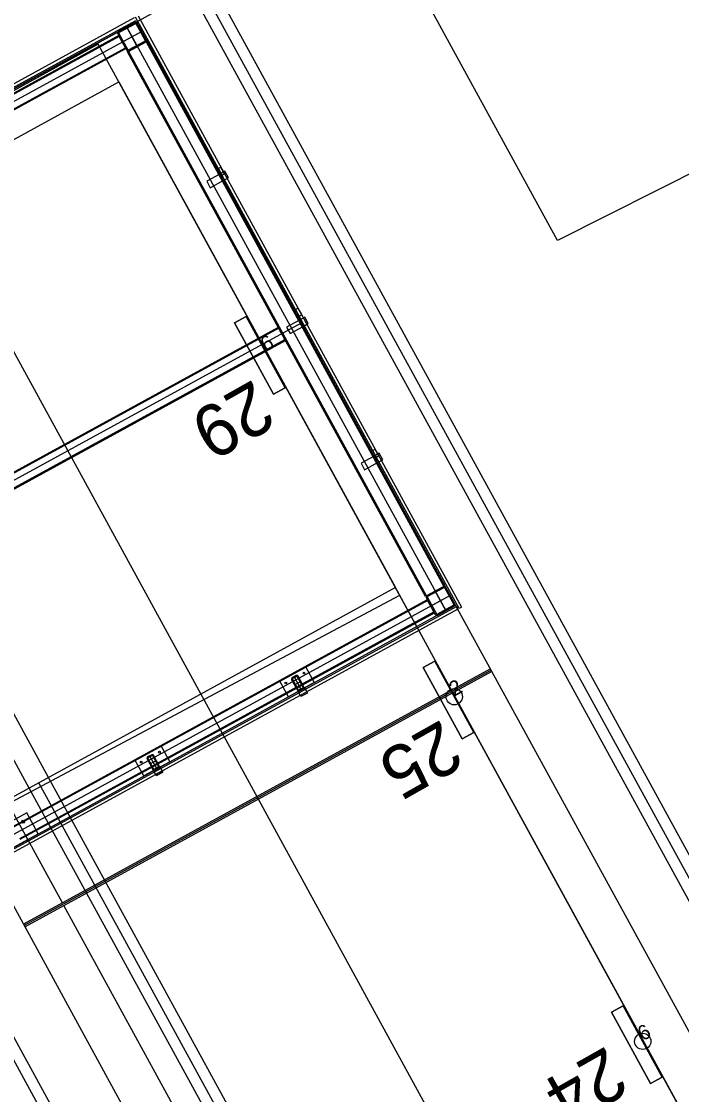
# Model space of a CAD drawing. Extents: x -783978 to -783565, y -1064821 to -1064596.
# Drawn here: x -783735.98 to -783731.52, y -1064671.69 to -1064664.43 of the extents above; entities that cross this region are included whole.
import ezdxf

# ---------------------------------------------------------------- set-up
doc = ezdxf.new("R2010")
doc.units = 0
for name, color, linetype in [('Default', 7, 'Continuous'), ('PS 01_01_10', 7, 'Continuous'), ('SO 01_20_01', 7, 'Continuous'), ('SO 01_50_01', 7, 'Continuous'), ('SO 01_74_01', 7, 'Continuous'), ('SO 01_86_04', 7, 'Continuous')]:
    doc.layers.add(name, color=color, linetype=linetype)

# ---------------------------------------------------------------- blocks, each defined once
blk = doc.blocks.new('POINT_DISPLAY')
at = {"layer": 'Default'}
blk.add_line((0, 0), (0, 0), dxfattribs=at)

msp = doc.modelspace()

# ---------------------------------------------------------------- linework, layer by layer
at = {"layer": 'PS 01_01_10'}
msp.add_lwpolyline([(-783718.9415, -1064658.9356), (-783725.9639, -1064662.6889), (-783732.3538, -1064665.9121), (-783735.2095, -1064660.6967), (-783789.362, -1064690.3481), (-783783.8255, -1064700.4409), (-783871.4362, -1064748.4249), (-783875.857, -1064749.8347)], dxfattribs=at)
at = {"layer": 'SO 01_20_01'}
for p, q in [((-783726.9264, -1064683.3119), (-783738.1468, -1064662.8034)), ((-783728.4298, -1064675.772), (-783734.7655, -1064664.1918)), ((-783728.357, -1064675.7488), (-783734.6997, -1064664.1558)), ((-783728.4886, -1064675.8208), (-783734.8312, -1064664.2278)), ((-783735.2041, -1064664.4318), (-783786.7885, -1064692.6541)), ((-783733.0442, -1064668.3796), (-783735.2041, -1064664.4318)), ((-783786.6445, -1064692.9173), (-783735.3233, -1064664.839)), ((-783735.3233, -1064664.839), (-783733.4514, -1064668.2604)), ((-783735.7981, -1064669.5443), (-783737.67, -1064666.1229)), ((-783735.9297, -1064669.6163), (-783737.8016, -1064666.1949)), ((-783733.4514, -1064668.2604), (-783745.2333, -1064674.7064)), ((-783733.0722, -1064668.9535), (-783733.4514, -1064668.2604)), ((-783745.0893, -1064674.9696), (-783733.0442, -1064668.3796)), ((-783726.0127, -1064681.2318), (-783733.0442, -1064668.3796)), ((-783732.809, -1064668.8095), (-783735.9673, -1064670.5374)), ((-783732.8042, -1064668.8182), (-783735.9625, -1064670.5461)), ((-783732.7994, -1064668.827), (-783735.9577, -1064670.5549)), ((-783726.2758, -1064681.3758), (-783733.0626, -1064668.971)), ((-783728.2804, -1064683.4414), (-783735.8639, -1064669.5803)), ((-783728.2146, -1064683.4054), (-783735.7981, -1064669.5443)), ((-783728.3462, -1064683.4774), (-783735.9297, -1064669.6163)), ((-783735.7041, -1064670.3934), (-783736.0833, -1064669.7003)), ((-783729.1709, -1064682.9597), (-783736.2025, -1064670.1075)), ((-783732.4653, -1064677.9799), (-783736.6411, -1064670.3475)), ((-783732.3925, -1064677.9567), (-783736.5753, -1064670.3115)), ((-783728.9074, -1064682.8156), (-783735.6946, -1064670.411))]:
    msp.add_line(p, q, dxfattribs=at)
at = {"layer": 'SO 01_50_01'}
for p, q in [((-783786.7885, -1064692.6541), (-783725.4827, -1064659.1131)), ((-783738.5378, -1064666.2557), (-783734.1523, -1064663.8564)), ((-783738.5378, -1064666.2558), (-783734.1522, -1064663.8565)), ((-783738.5378, -1064666.2558), (-783734.1522, -1064663.8565))]:
    msp.add_line(p, q, dxfattribs=at)
at = {"layer": 'SO 01_74_01'}
for p, q in [((-783735.2185, -1064664.4055), (-783786.6099, -1064692.5222)), ((-783786.6003, -1064692.5398), (-783735.2089, -1064664.423)), ((-783733.0211, -1064668.4011), (-783735.2097, -1064664.4007)), ((-783735.1922, -1064664.3911), (-783733.0035, -1064668.3915)), ((-783735.3237, -1064664.5257), (-783738.1265, -1064666.0592)), ((-783735.3207, -1064664.5313), (-783738.1235, -1064666.0647)), ((-783735.2757, -1064664.6135), (-783735.3237, -1064664.5257)), ((-783735.2787, -1064664.608), (-783735.3207, -1064664.5313)), ((-783735.2637, -1064664.6354), (-783735.1321, -1064664.5634)), ((-783735.2567, -1064664.6316), (-783735.1391, -1064664.5673)), ((-783735.1391, -1064664.5673), (-783733.1232, -1064668.2518)), ((-783735.1321, -1064664.5634), (-783733.1162, -1064668.248)), ((-783738.0815, -1064666.1414), (-783735.2787, -1064664.608)), ((-783738.0785, -1064666.1469), (-783735.2757, -1064664.6135)), ((-783733.2478, -1064668.32), (-783735.2637, -1064664.6354)), ((-783733.2408, -1064668.3162), (-783735.2567, -1064664.6316)), ((-783734.6318, -1064665.4153), (-783734.6494, -1064665.4249)), ((-783734.6494, -1064665.4249), (-783734.6254, -1064665.4688)), ((-783734.605, -1064665.4434), (-783734.6401, -1064665.4626)), ((-783734.6078, -1064665.4592), (-783734.6318, -1064665.4153)), ((-783734.581, -1064665.4873), (-783734.605, -1064665.4434)), ((-783734.6401, -1064665.4626), (-783734.6161, -1064665.5065)), ((-783734.6254, -1064665.4688), (-783734.6078, -1064665.4592)), ((-783734.6161, -1064665.5065), (-783734.581, -1064665.4873)), ((-783734.1098, -1064666.3694), (-783734.1274, -1064666.379)), ((-783734.1274, -1064666.379), (-783734.1034, -1064666.4228)), ((-783734.0858, -1064666.4132), (-783734.1098, -1064666.3694)), ((-783734.1034, -1064666.4228), (-783734.0858, -1064666.4132)), ((-783734.0651, -1064666.4304), (-783734.1002, -1064666.4496)), ((-783734.1002, -1064666.4496), (-783734.0762, -1064666.4934)), ((-783734.0411, -1064666.4742), (-783734.0651, -1064666.4304)), ((-783734.2438, -1064666.4996), (-783737.0465, -1064668.0331)), ((-783734.2407, -1064666.5052), (-783737.0435, -1064668.0386)), ((-783734.1958, -1064666.5874), (-783734.2438, -1064666.4996)), ((-783734.1988, -1064666.5818), (-783734.2407, -1064666.5052)), ((-783734.0762, -1064666.4934), (-783734.0411, -1064666.4742)), ((-783737.0016, -1064668.1153), (-783734.1988, -1064666.5818)), ((-783736.9985, -1064668.1208), (-783734.1958, -1064666.5874)), ((-783733.5879, -1064667.3234), (-783733.6054, -1064667.333)), ((-783733.6054, -1064667.333), (-783733.5814, -1064667.3769)), ((-783733.5639, -1064667.3673), (-783733.5879, -1064667.3234)), ((-783733.5611, -1064667.3515), (-783733.5962, -1064667.3707)), ((-783733.5962, -1064667.3707), (-783733.5722, -1064667.4146)), ((-783733.5814, -1064667.3769), (-783733.5639, -1064667.3673)), ((-783733.5722, -1064667.4146), (-783733.5371, -1064667.3954)), ((-783733.5371, -1064667.3954), (-783733.5611, -1064667.3515)), ((-783733.1162, -1064668.248), (-783733.2478, -1064668.32)), ((-783733.1232, -1064668.2518), (-783733.2408, -1064668.3162)), ((-783733.2358, -1064668.3419), (-783736.0386, -1064669.8754)), ((-783733.2328, -1064668.3475), (-783736.0356, -1064669.8809)), ((-783733.1878, -1064668.4297), (-783733.2358, -1064668.3419)), ((-783733.1908, -1064668.4241), (-783733.2328, -1064668.3475)), ((-783744.8433, -1064674.8464), (-783733.0394, -1064668.3884)), ((-783733.0298, -1064668.4059), (-783744.8337, -1064674.8639)), ((-783733.0394, -1064668.3884), (-783733.0298, -1064668.4059)), ((-783733.0035, -1064668.3915), (-783733.0211, -1064668.4011)), ((-783735.9936, -1064669.9576), (-783733.1908, -1064668.4241)), ((-783735.9906, -1064669.9631), (-783733.1878, -1064668.4297)), ((-783734.1101, -1064668.9628), (-783734.0663, -1064668.9388)), ((-783734.0909, -1064668.9979), (-783734.1101, -1064668.9628)), ((-783734.1053, -1064668.9715), (-783734.0615, -1064668.9475)), ((-783734.0957, -1064668.9891), (-783734.1053, -1064668.9715)), ((-783734.0519, -1064668.9651), (-783734.0957, -1064668.9891)), ((-783734.0471, -1064668.9739), (-783734.0909, -1064668.9979)), ((-783734.0663, -1064668.9388), (-783734.0471, -1064668.9739)), ((-783734.0615, -1064668.9475), (-783734.0519, -1064668.9651)), ((-783735.0883, -1064669.4979), (-783735.0444, -1064669.4739)), ((-783735.0691, -1064669.533), (-783735.0883, -1064669.4979)), ((-783735.0835, -1064669.5067), (-783735.0396, -1064669.4827)), ((-783735.0739, -1064669.5243), (-783735.0835, -1064669.5067)), ((-783735.03, -1064669.5003), (-783735.0739, -1064669.5243)), ((-783735.0252, -1064669.509), (-783735.0691, -1064669.533)), ((-783735.0444, -1064669.4739), (-783735.0252, -1064669.509)), ((-783735.0396, -1064669.4827), (-783735.03, -1064669.5003))]:
    msp.add_line(p, q, dxfattribs=at)
for points in [[(-783735.1681, -1064664.4976), (-783787.4762, -1064693.1159)], [(-783735.2146, -1064664.4376), (-783735.3252, -1064664.4981)], [(-783735.2108, -1064664.4446), (-783735.3213, -1064664.5051)], [(-783735.1681, -1064664.4976), (-783735.2997, -1064664.5696)], [(-783735.2699, -1064664.4678), (-783733.11, -1064668.4156)], [(-783735.1979, -1064664.5994), (-783735.2699, -1064664.4678)], [(-783735.1449, -1064664.5567), (-783735.2054, -1064664.4462)], [(-783735.1379, -1064664.5529), (-783735.1983, -1064664.4423)], [(-783735.3299, -1064664.5143), (-783735.2695, -1064664.6249)], [(-783735.3229, -1064664.5105), (-783735.2624, -1064664.621)], [(-783735.257, -1064664.6226), (-783735.1465, -1064664.5622)], [(-783735.2532, -1064664.6297), (-783735.1426, -1064664.5692)], [(-783734.0882, -1064666.4715), (-783786.3963, -1064695.0898)], [(-783733.1268, -1064668.2538), (-783733.2373, -1064668.3142)], [(-783733.1229, -1064668.2608), (-783733.2334, -1064668.3213)], [(-783733.057, -1064668.3729), (-783733.1175, -1064668.2624)], [(-783733.05, -1064668.3691), (-783733.1105, -1064668.2585)], [(-783733.0802, -1064668.3138), (-783745.8491, -1064675.2998)], [(-783733.2421, -1064668.3305), (-783733.1816, -1064668.4411)], [(-783733.235, -1064668.3267), (-783733.1746, -1064668.4372)], [(-783733.0802, -1064668.3138), (-783733.2118, -1064668.3858)], [(-783733.11, -1064668.4156), (-783733.182, -1064668.284)], [(-783733.1691, -1064668.4388), (-783733.0586, -1064668.3783)], [(-783733.1653, -1064668.4458), (-783733.0548, -1064668.3854)], [(-783734.1226, -1064668.8556), (-783734.1498, -1064668.8705)], [(-783734.1536, -1064668.8833), (-783734.1147, -1064668.9545)], [(-783734.1481, -1064668.8803), (-783734.1091, -1064668.9515)], [(-783734.1195, -1064668.8611), (-783734.1468, -1064668.876)], [(-783734.1362, -1064668.863), (-783734.0882, -1064668.9508)], [(-783734.0903, -1064668.8949), (-783734.1341, -1064668.9189)], [(-783734.0763, -1064668.9335), (-783734.1153, -1064668.8624)], [(-783734.0708, -1064668.9305), (-783734.1097, -1064668.8593)], [(-783734.1049, -1064668.9527), (-783734.0776, -1064668.9378)], [(-783734.1018, -1064668.9582), (-783734.0746, -1064668.9433)], [(-783735.1318, -1064669.4185), (-783735.0928, -1064669.4896)], [(-783735.1007, -1064669.3907), (-783735.128, -1064669.4057)], [(-783735.1262, -1064669.4155), (-783735.0873, -1064669.4866)], [(-783735.0977, -1064669.3963), (-783735.125, -1064669.4112)], [(-783735.1144, -1064669.3982), (-783735.0664, -1064669.4859)], [(-783735.0684, -1064669.4301), (-783735.1123, -1064669.4541)], [(-783735.0545, -1064669.4687), (-783735.0934, -1064669.3975)], [(-783735.049, -1064669.4656), (-783735.0879, -1064669.3945)], [(-783735.083, -1064669.4879), (-783735.0558, -1064669.4729)], [(-783735.08, -1064669.4934), (-783735.0527, -1064669.4785)]]:
    msp.add_lwpolyline(points, dxfattribs=at)
for points in [[(-783734.6161, -1064665.5065), (-783734.6401, -1064665.4626), (-783734.7279, -1064665.5106), (-783734.7039, -1064665.5545)], [(-783734.0762, -1064666.4934), (-783734.1002, -1064666.4496), (-783734.1879, -1064666.4976), (-783734.1639, -1064666.5414)], [(-783733.5722, -1064667.4146), (-783733.5962, -1064667.3707), (-783733.6839, -1064667.4187), (-783733.6599, -1064667.4626)], [(-783734.0005, -1064668.9028), (-783734.1759, -1064668.9988), (-783734.2335, -1064668.8935), (-783734.0581, -1064668.7975)], [(-783734.9786, -1064669.4379), (-783735.1541, -1064669.5339), (-783735.2117, -1064669.4287), (-783735.0362, -1064669.3327)], [(-783735.9459, -1064669.7847), (-783736.2968, -1064669.9767), (-783736.22, -1064670.1171), (-783735.8691, -1064669.9251)]]:
    msp.add_lwpolyline(points, close=True, dxfattribs=at)
for centre, radius in [((-783734.07, -1064668.8382), 0.006), ((-783734.1928, -1064668.9054), 0.006), ((-783735.171, -1064669.4406), 0.006), ((-783735.0482, -1064669.3734), 0.006), ((-783735.9705, -1064669.8438), 0.01)]:
    msp.add_circle(centre, radius, dxfattribs=at)
for centre, radius, start, end in [((-783735.3194, -1064664.5086), 0.012, 118.68349, 208.68349), ((-783735.2089, -1064664.4481), 0.012, 28.68349, 118.68349), ((-783735.2089, -1064664.4481), 0.004, 28.68349, 118.68349), ((-783735.3194, -1064664.5086), 0.004, 118.68349, 208.68349), ((-783735.1484, -1064664.5586), 0.004, 298.68349, 28.68349), ((-783735.1484, -1064664.5586), 0.012, 298.68349, 28.68349), ((-783735.2589, -1064664.6191), 0.012, 208.68349, 298.68349), ((-783735.2589, -1064664.6191), 0.004, 208.68349, 298.68349), ((-783733.121, -1064668.2643), 0.012, 28.68349, 118.68349), ((-783733.121, -1064668.2643), 0.004, 28.68349, 118.68349), ((-783733.2315, -1064668.3248), 0.012, 118.68349, 208.68349), ((-783733.2315, -1064668.3248), 0.004, 118.68349, 208.68349), ((-783733.0605, -1064668.3748), 0.004, 298.68349, 28.68349), ((-783733.0605, -1064668.3748), 0.012, 298.68349, 28.68349), ((-783733.1711, -1064668.4353), 0.012, 208.68349, 298.68349), ((-783733.1711, -1064668.4353), 0.004, 208.68349, 298.68349), ((-783734.118, -1064668.8639), 0.00945, 28.68349, 118.68349), ((-783734.1453, -1064668.8788), 0.00945, 118.68349, 208.68349), ((-783734.1453, -1064668.8788), 0.00315, 118.68349, 208.68349), ((-783734.118, -1064668.8639), 0.00315, 28.68349, 118.68349), ((-783734.1064, -1064668.9499), 0.00945, 208.68349, 298.68349), ((-783734.1064, -1064668.9499), 0.00315, 208.68349, 298.68349), ((-783734.0791, -1064668.935), 0.00315, 298.68349, 28.68349), ((-783734.0791, -1064668.935), 0.00945, 298.68349, 28.68349), ((-783735.1235, -1064669.414), 0.00945, 118.68349, 208.68349), ((-783735.1235, -1064669.414), 0.00315, 118.68349, 208.68349), ((-783735.0962, -1064669.399), 0.00945, 28.68349, 118.68349), ((-783735.0962, -1064669.399), 0.00315, 28.68349, 118.68349), ((-783735.0845, -1064669.4851), 0.00945, 208.68349, 298.68349), ((-783735.0845, -1064669.4851), 0.00315, 208.68349, 298.68349), ((-783735.0573, -1064669.4702), 0.00315, 298.68349, 28.68349), ((-783735.0573, -1064669.4702), 0.00945, 298.68349, 28.68349)]:
    msp.add_arc(centre, radius, start, end, dxfattribs=at)
at = {"layer": 'SO 01_86_04'}
for p, q in [((-783734.5403, -1064666.4684), (-783734.4614, -1064666.4252)), ((-783734.4614, -1064666.4252), (-783734.5403, -1064666.4684)), ((-783734.5403, -1064666.4684), (-783734.4614, -1064666.4252)), ((-783734.4614, -1064666.4252), (-783734.5403, -1064666.4684)), ((-783734.4614, -1064666.4252), (-783734.1974, -1064666.9077)), ((-783734.1974, -1064666.9077), (-783734.4614, -1064666.4252)), ((-783734.4614, -1064666.4252), (-783734.1974, -1064666.9077)), ((-783734.1974, -1064666.9077), (-783734.4614, -1064666.4252)), ((-783734.2763, -1064666.9509), (-783734.5403, -1064666.4684)), ((-783734.5403, -1064666.4684), (-783734.2763, -1064666.9509)), ((-783734.5403, -1064666.4684), (-783734.2763, -1064666.9509)), ((-783734.2763, -1064666.9509), (-783734.5403, -1064666.4684)), ((-783734.1974, -1064666.9077), (-783734.2763, -1064666.9509)), ((-783734.2763, -1064666.9509), (-783734.1974, -1064666.9077)), ((-783734.1974, -1064666.9077), (-783734.2763, -1064666.9509)), ((-783734.2763, -1064666.9509), (-783734.1974, -1064666.9077)), ((-783733.2646, -1064668.8002), (-783733.1856, -1064668.757)), ((-783733.1856, -1064668.757), (-783733.2646, -1064668.8002)), ((-783733.2646, -1064668.8002), (-783733.1856, -1064668.757)), ((-783733.1856, -1064668.757), (-783733.2646, -1064668.8002)), ((-783733.1856, -1064668.757), (-783732.9216, -1064669.2395)), ((-783732.9216, -1064669.2395), (-783733.1856, -1064668.757)), ((-783733.1856, -1064668.757), (-783732.9216, -1064669.2395)), ((-783732.9216, -1064669.2395), (-783733.1856, -1064668.757)), ((-783733.0006, -1064669.2827), (-783733.2646, -1064668.8002)), ((-783733.2646, -1064668.8002), (-783733.0006, -1064669.2827)), ((-783733.2646, -1064668.8002), (-783733.0006, -1064669.2827)), ((-783733.0006, -1064669.2827), (-783733.2646, -1064668.8002)), ((-783732.9216, -1064669.2395), (-783733.0006, -1064669.2827)), ((-783733.0006, -1064669.2827), (-783732.9216, -1064669.2395)), ((-783732.9216, -1064669.2395), (-783733.0006, -1064669.2827)), ((-783733.0006, -1064669.2827), (-783732.9216, -1064669.2395)), ((-783731.9888, -1064671.132), (-783731.9099, -1064671.0888)), ((-783731.9099, -1064671.0888), (-783731.9888, -1064671.132)), ((-783731.9888, -1064671.132), (-783731.9099, -1064671.0888)), ((-783731.9099, -1064671.0888), (-783731.9888, -1064671.132)), ((-783731.9099, -1064671.0888), (-783731.6459, -1064671.5713)), ((-783731.6459, -1064671.5713), (-783731.9099, -1064671.0888)), ((-783731.9099, -1064671.0888), (-783731.6459, -1064671.5713)), ((-783731.6459, -1064671.5713), (-783731.9099, -1064671.0888)), ((-783731.7249, -1064671.6145), (-783731.9888, -1064671.132)), ((-783731.9888, -1064671.132), (-783731.7249, -1064671.6145)), ((-783731.9888, -1064671.132), (-783731.7249, -1064671.6145)), ((-783731.7249, -1064671.6145), (-783731.9888, -1064671.132)), ((-783731.6459, -1064671.5713), (-783731.7249, -1064671.6145)), ((-783731.7249, -1064671.6145), (-783731.6459, -1064671.5713)), ((-783731.6459, -1064671.5713), (-783731.7249, -1064671.6145)), ((-783731.7249, -1064671.6145), (-783731.6459, -1064671.5713))]:
    msp.add_line(p, q, dxfattribs=at)
for points in [[(-783735.4626, -1064664.5844), (-783749.7616, -1064672.4637), (-783749.643, -1064672.6735)], [(-783718.4346, -1064695.4446), (-783718.5614, -1064695.5192), (-783725.2526, -1064683.2773), (-783728.2152, -1064677.831), (-783729.7032, -1064675.1114), (-783731.1911, -1064672.3918), (-783732.679, -1064669.6722), (-783734.1669, -1064666.9527), (-783735.4626, -1064664.5844)], [(-783733.4229, -1064668.3125), (-783737.6471, -1064670.5617), (-783739.9521, -1064671.817), (-783742.6942, -1064673.3169), (-783745.0268, -1064674.6345), (-783745.4136, -1064673.9496)]]:
    msp.add_lwpolyline(points, dxfattribs=at)
for centre in [(-783733.0536, -1064668.9983), (-783731.7779, -1064671.3301)]:
    msp.add_circle(centre, 0.0549, dxfattribs=at)

# ---------------------------------------------------------------- block references
at = {"layer": 'SO 01_86_04', "xscale": 0.010000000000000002, "yscale": 0.009999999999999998, "rotation": 28.683491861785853}
for p in [(-783734.4614, -1064666.4252), (-783734.4614, -1064666.4252), (-783734.5403, -1064666.4684), (-783734.5403, -1064666.4684), (-783734.4083, -1064666.7097), (-783734.2763, -1064666.9509), (-783734.2763, -1064666.9509), (-783734.1974, -1064666.9077), (-783734.1974, -1064666.9077), (-783733.1856, -1064668.757), (-783733.1856, -1064668.757), (-783733.2646, -1064668.8002), (-783733.2646, -1064668.8002), (-783733.1326, -1064669.0415), (-783733.0006, -1064669.2827), (-783733.0006, -1064669.2827), (-783732.9216, -1064669.2395), (-783732.9216, -1064669.2395), (-783731.9099, -1064671.0888), (-783731.9099, -1064671.0888), (-783731.9888, -1064671.132), (-783731.9888, -1064671.132), (-783731.8569, -1064671.3733), (-783731.7249, -1064671.6145), (-783731.7249, -1064671.6145), (-783731.6459, -1064671.5713), (-783731.6459, -1064671.5713)]:
    msp.add_blockref('POINT_DISPLAY', p, dxfattribs=at)

# ---------------------------------------------------------------- texts
at = {"layer": 'SO 01_86_04'}
for s, height, rotation, p in [('6', 0.1, 28.68349, (-783734.3294, -1064666.6665)), ('29', 0.351, 209.46001, (-783734.4084, -1064666.847)), ('2', 0.1, 28.68349, (-783733.0536, -1064668.9983)), ('25', 0.351, 209.46001, (-783733.1363, -1064669.1478)), ('6', 0.1, 28.68349, (-783731.7779, -1064671.3301)), ('24', 0.351, 209.46001, (-783732.0208, -1064671.3574))]:
    msp.add_text(s, height=height, rotation=rotation, dxfattribs=at).set_placement(p)

doc.saveas('drawing.dxf')
